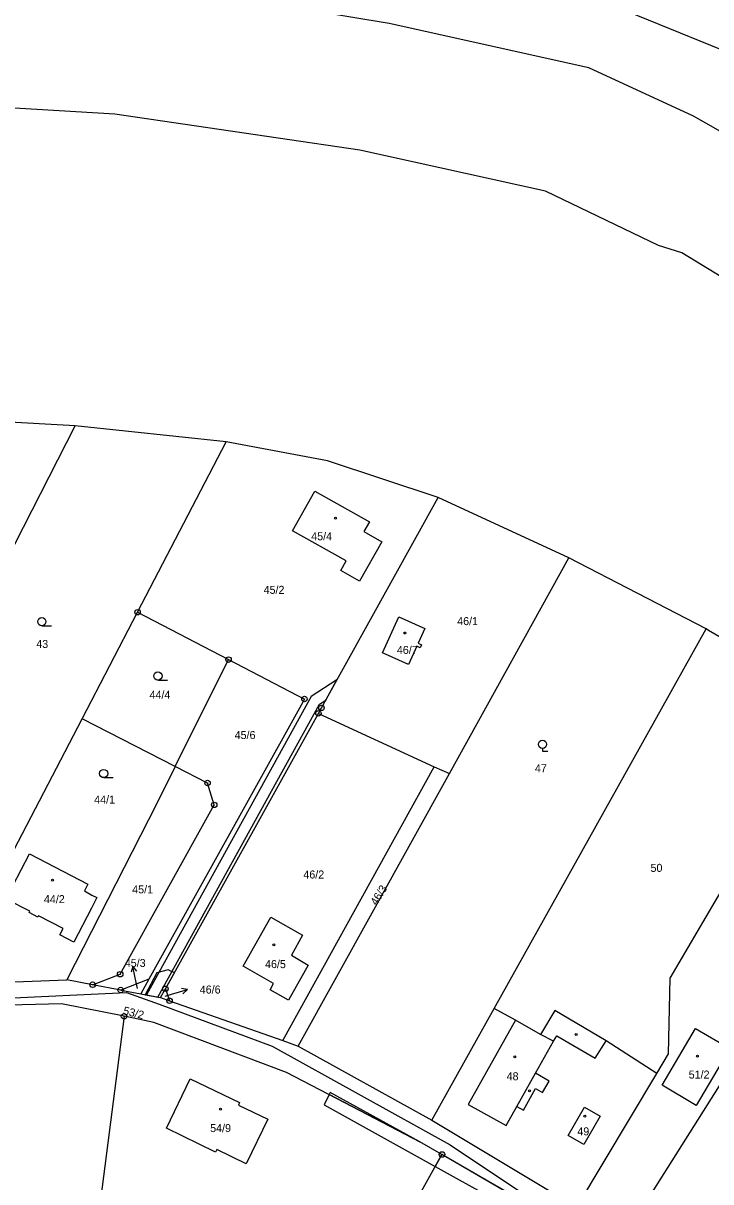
# Model space of a CAD drawing. Extents: x -587171 to -555306, y -1167727 to -1074732.
# Drawn here: x -559460.4 to -559335, y -1076430.8 to -1076219.5 of the extents above; entities that cross this region are included whole.
import ezdxf

# ---------------------------------------------------------------- set-up
doc = ezdxf.new("R2010")
doc.units = 0
for name, color, linetype in [('Hranice parcel', 7, 'Continuous'), ('Parcelní čísla', 7, 'Continuous'), ('Pop  PČ popisy', 7, 'Continuous'), ('Vnitřní kresba', 7, 'Continuous'), ('Věcná břemena k části', 7, 'Continuous'), ('Značky bodu BP', 7, 'Continuous'), ('Značky budov', 7, 'Continuous'), ('Značky kultur', 7, 'Continuous')]:
    doc.layers.add(name, color=color, linetype=linetype)

msp = doc.modelspace()

# ---------------------------------------------------------------- linework, layer by layer
at = {"layer": 'Hranice parcel'}
for p, q in [((-559450.92, -1076292.94), (-559473.66, -1076291.66)), ((-559485.29, -1076360.22), (-559450.92, -1076292.94)), ((-559423.37, -1076295.86), (-559450.92, -1076292.94)), ((-559439.53, -1076326.91), (-559423.37, -1076295.86)), ((-559360.86, -1076317.01), (-559384.7, -1076305.99)), ((-559382.67, -1076356.34), (-559360.86, -1076317.01)), ((-559335.84, -1076329.97), (-559360.86, -1076317.01)), ((-559449.65, -1076346.36), (-559439.53, -1076326.91)), ((-559439.53, -1076326.91), (-559422.93, -1076335.55)), ((-559374.52, -1076399.19), (-559335.84, -1076329.97)), ((-559432.65, -1076355.05), (-559422.93, -1076335.55)), ((-559462.83, -1076371.7), (-559449.65, -1076346.36)), ((-559432.65, -1076355.05), (-559449.65, -1076346.36)), ((-559434.45, -1076395.58), (-559406.54, -1076345.35)), ((-559406.54, -1076345.35), (-559385.42, -1076355.09)), ((-559295.54, -1076353.12), (-559351, -1076441.05)), ((-559432.65, -1076355.05), (-559436.02, -1076361.81)), ((-559426.76, -1076358.06), (-559432.65, -1076355.05)), ((-559413.05, -1076404.98), (-559385.42, -1076355.09)), ((-559385.42, -1076355.09), (-559382.67, -1076356.34)), ((-559410.23, -1076406.03), (-559382.67, -1076356.34)), ((-559436.02, -1076361.81), (-559452.4, -1076393.96)), ((-559474.85, -1076394.79), (-559452.4, -1076393.96)), ((-559447.72, -1076394.84), (-559452.4, -1076393.96)), ((-559442.6, -1076395.81), (-559447.72, -1076394.84)), ((-559437.47, -1076393.81), (-559442.6, -1076395.81)), ((-559442.6, -1076395.81), (-559438.96, -1076396.5)), ((-559437.47, -1076393.81), (-559438.96, -1076396.5)), ((-559435.34, -1076397.19), (-559434.45, -1076395.58)), ((-559434.45, -1076395.58), (-559433.69, -1076397.77)), ((-559438.96, -1076396.5), (-559435.34, -1076397.19)), ((-559435.34, -1076397.19), (-559433.69, -1076397.77)), ((-559433.69, -1076397.77), (-559413.05, -1076404.98)), ((-559385.89, -1076419.53), (-559374.52, -1076399.19)), ((-559413.05, -1076404.98), (-559410.23, -1076406.03)), ((-559410.23, -1076406.03), (-559385.89, -1076419.53)), ((-559359.39, -1076435.43), (-559344.86, -1076411.02)), ((-559385.89, -1076419.53), (-559359.39, -1076435.43)), ((-559352.65, -1076443.99), (-559384.02, -1076425.8))]:
    msp.add_line(p, q, dxfattribs=at)
for points in [[(-559593.42, -1076182.87), (-559554.97, -1076187.73), (-559493.51, -1076194.91), (-559433.37, -1076199.67), (-559391.72, -1076206.93), (-559355.84, -1076215.01), (-559333.07, -1076224.29), (-559296.15, -1076244.56), (-559247.71, -1076272.7)], [(-559240.39, -1076291.92), (-559338.12, -1076236.45), (-559357.23, -1076227.62), (-559393.62, -1076219.58), (-559434.86, -1076212.68), (-559494.41, -1076207.65), (-559564.79, -1076200.53)], [(-559252.7, -1076313.31), (-559286.15, -1076294.4), (-559340.28, -1076261.35), (-559344.5, -1076260.04), (-559365.15, -1076250.12), (-559399.01, -1076242.66), (-559443.7, -1076236.06), (-559507.72, -1076232.26), (-559566.42, -1076228.54)], [(-559384.7, -1076305.99), (-559404.88, -1076299.33), (-559423.37, -1076295.86)], [(-559401.51, -1076317.56), (-559411.27, -1076312.04), (-559407.2, -1076304.83), (-559397.26, -1076310.44), (-559398.26, -1076312.21), (-559394.97, -1076314.08), (-559399.03, -1076321.24), (-559402.48, -1076319.3), (-559401.51, -1076317.56)], [(-559406.54, -1076345.35), (-559406, -1076344.36), (-559384.7, -1076305.99)], [(-559387.98, -1076333.38), (-559388.6, -1076333.09), (-559390.13, -1076336.47), (-559394.87, -1076334.33), (-559391.86, -1076327.73), (-559387.16, -1076329.87), (-559388.36, -1076332.55), (-559387.73, -1076332.83), (-559387.98, -1076333.38)], [(-559312.85, -1076343.32), (-559335.4, -1076330.22), (-559335.84, -1076329.97)], [(-559422.93, -1076335.55), (-559409.1, -1076342.74), (-559437.47, -1076393.81)], [(-559344.86, -1076411.02), (-559342.72, -1076407.42), (-559342.37, -1076393.65), (-559312.85, -1076343.32)], [(-559447.72, -1076394.84), (-559442.7, -1076392.93), (-559425.55, -1076362.04), (-559426.76, -1076358.06)], [(-559463.52, -1076379.86), (-559463.8, -1076379.72), (-559459.23, -1076370.97), (-559448.61, -1076376.51), (-559449.22, -1076377.74), (-559447.84, -1076378.53), (-559446.95, -1076378.95), (-559447.91, -1076380.86), (-559451.16, -1076387.1), (-559453.69, -1076385.74), (-559453.11, -1076384.6), (-559457.61, -1076382.26), (-559457.73, -1076382.49), (-559459.31, -1076381.68), (-559459.2, -1076381.43), (-559463.22, -1076379.34), (-559463.52, -1076379.86)], [(-559420.28, -1076391.46), (-559415.25, -1076382.52), (-559409.44, -1076385.79), (-559411.46, -1076389.45), (-559408.41, -1076391.29), (-559412, -1076397.63), (-559415.35, -1076395.75), (-559414.72, -1076394.61), (-559420.28, -1076391.46)], [(-559529.43, -1076404.66), (-559482.86, -1076398.2), (-559441.57, -1076396.27), (-559435.57, -1076398.37), (-559414.99, -1076406.03), (-559382.52, -1076424.05), (-559352.65, -1076443.99)], [(-559441.99, -1076400.6), (-559453.4, -1076398.3), (-559474.91, -1076398.9), (-559504.91, -1076402.3), (-559529.43, -1076404.66)], [(-559344.86, -1076411.02), (-559354.09, -1076405.07), (-559363.41, -1076399.53), (-559366.07, -1076403.89), (-559370.59, -1076401.33), (-559374.52, -1076399.19)], [(-559441.99, -1076400.6), (-559446.45, -1076435.47), (-559446.5, -1076435.86)], [(-559384.02, -1076425.8), (-559388.04, -1076423.47), (-559412.35, -1076410.85), (-559436.57, -1076401.7), (-559441.99, -1076400.6)], [(-559331.54, -1076406.48), (-559337.64, -1076416.85), (-559343.84, -1076413.18), (-559337.75, -1076402.82), (-559331.54, -1076406.48)], [(-559415.77, -1076419.38), (-559419.7, -1076427.51), (-559425.07, -1076424.91), (-559425.29, -1076425.36), (-559434.28, -1076421.01), (-559429.91, -1076411.99), (-559420.92, -1076416.32), (-559421.14, -1076416.78), (-559415.77, -1076419.38)], [(-559355.14, -1076418.79), (-559358.12, -1076423.99), (-559360.98, -1076422.33), (-559358.05, -1076417.14), (-559355.14, -1076418.79)], [(-559402.27, -1076458.62), (-559385, -1076427.56), (-559384.02, -1076425.8)]]:
    msp.add_lwpolyline(points, dxfattribs=at)
at = {"layer": 'Pop  PČ popisy'}
for p, q in [((-559440.42, -1076391.49), (-559440.71, -1076392.57)), ((-559439.8, -1076394.42), (-559440.42, -1076391.49)), ((-559440.42, -1076391.49), (-559439.73, -1076392.36)), ((-559439.57, -1076395.52), (-559439.8, -1076394.42)), ((-559433.32, -1076396.55), (-559430.44, -1076395.72)), ((-559430.44, -1076395.72), (-559431.54, -1076395.52)), ((-559430.44, -1076395.72), (-559431.26, -1076396.48)), ((-559434.52, -1076396.9), (-559433.32, -1076396.55))]:
    msp.add_line(p, q, dxfattribs=at)
at = {"layer": 'Vnitřní kresba'}
for p, q in [((-559370.59, -1076401.33), (-559379.25, -1076416.66)), ((-559363.68, -1076405.15), (-559366.07, -1076403.89)), ((-559363.68, -1076405.15), (-559363.09, -1076404.16)), ((-559363.09, -1076404.16), (-559356.09, -1076408.26)), ((-559366.97, -1076410.99), (-559363.68, -1076405.15)), ((-559356.09, -1076408.26), (-559354.09, -1076405.07)), ((-559370.37, -1076417.03), (-559366.97, -1076410.99)), ((-559364.47, -1076412.41), (-559366.97, -1076410.99)), ((-559365.67, -1076414.47), (-559364.47, -1076412.41)), ((-559369.17, -1076417.71), (-559366.96, -1076413.76)), ((-559366.96, -1076413.76), (-559365.67, -1076414.47)), ((-559379.25, -1076416.66), (-559372.33, -1076420.51)), ((-559372.33, -1076420.51), (-559370.37, -1076417.03)), ((-559370.37, -1076417.03), (-559369.17, -1076417.71))]:
    msp.add_line(p, q, dxfattribs=at)
at = {"layer": 'Věcná břemena k části'}
for points in [[(-559437.93, -1076396.7), (-559435.86, -1076397.09), (-559406.36, -1076343.68), (-559405.21, -1076342.95), (-559403.17, -1076339.27), (-559407.87, -1076342.27)], [(-559438.12, -1076396.66), (-559435.34, -1076397.19), (-559434.45, -1076395.58), (-559432.82, -1076392.66), (-559433.93, -1076392.15), (-559436.04, -1076392.69)], [(-559404.39, -1076414.49), (-559404.58, -1076414.88), (-559388.04, -1076423.47)], [(-559385.24, -1076428), (-559384.02, -1076425.8), (-559388.04, -1076423.47), (-559404.58, -1076414.88), (-559405.51, -1076416.76)], [(-559353.75, -1076445.05), (-559353.12, -1076443.72), (-559367.42, -1076435.42), (-559384.02, -1076425.8), (-559385.24, -1076428), (-559374.75, -1076433.82), (-559373.73, -1076434.09)]]:
    msp.add_lwpolyline(points, close=True, dxfattribs=at)
at = {"layer": 'Značky bodu BP'}
for centre, radius in [((-559439.53, -1076326.91), 0.5), ((-559439.53, -1076326.91), 0.0303), ((-559422.93, -1076335.55), 0.5), ((-559422.93, -1076335.55), 0.0303), ((-559409.1, -1076342.74), 0.5), ((-559409.1, -1076342.74), 0.0303), ((-559406.54, -1076345.35), 0.5), ((-559406, -1076344.36), 0.5), ((-559406, -1076344.36), 0.0303), ((-559406.54, -1076345.35), 0.0303), ((-559426.76, -1076358.06), 0.5), ((-559426.76, -1076358.06), 0.0303), ((-559425.55, -1076362.04), 0.5), ((-559425.55, -1076362.04), 0.0303), ((-559442.7, -1076392.93), 0.5), ((-559442.7, -1076392.93), 0.0303), ((-559447.72, -1076394.84), 0.5), ((-559447.72, -1076394.84), 0.0303), ((-559442.6, -1076395.81), 0.5), ((-559442.6, -1076395.81), 0.0303), ((-559434.45, -1076395.58), 0.5), ((-559434.45, -1076395.58), 0.0303), ((-559433.69, -1076397.77), 0.5), ((-559433.69, -1076397.77), 0.0303), ((-559441.99, -1076400.6), 0.5), ((-559441.99, -1076400.6), 0.0303), ((-559384.02, -1076425.8), 0.5), ((-559384.02, -1076425.8), 0.0303)]:
    msp.add_circle(centre, radius, dxfattribs=at)
at = {"layer": 'Značky budov'}
for centre in [(-559403.44, -1076309.75), (-559390.76, -1076330.7), (-559455.02, -1076375.77), (-559414.66, -1076387.56), (-559359.56, -1076403.92), (-559370.75, -1076407.98), (-559337.44, -1076407.85), (-559368.03, -1076414.18), (-559424.39, -1076417.55), (-559357.97, -1076418.82)]:
    msp.add_circle(centre, 0.175, dxfattribs=at)
at = {"layer": 'Značky kultur'}
for p, q in [((-559456.99, -1076329.38), (-559455.24, -1076329.38)), ((-559435.82, -1076339.29), (-559434.07, -1076339.29)), ((-559365.68, -1076351.75), (-559365.68, -1076352.25)), ((-559365.68, -1076352.25), (-559364.68, -1076352.25)), ((-559445.7, -1076357.08), (-559443.95, -1076357.08))]:
    msp.add_line(p, q, dxfattribs=at)
for centre in [(-559456.99, -1076328.63), (-559435.82, -1076338.54), (-559365.68, -1076351), (-559445.7, -1076356.33)]:
    msp.add_circle(centre, 0.75, dxfattribs=at)

# ---------------------------------------------------------------- texts
at = {"layer": 'Parcelní čísla'}
for s, p in [('45/4', (-559407.86, -1076313.79)), ('45/2', (-559416.54, -1076323.56)), ('46/1', (-559381.24, -1076329.26)), ('43', (-559458, -1076333.43)), ('46/7', (-559392.24, -1076334.52)), ('44/4', (-559437.35, -1076342.7)), ('45/6', (-559421.82, -1076350.03)), ('47', (-559367.07, -1076356.09)), ('44/1', (-559447.44, -1076361.8)), ('46/2', (-559409.29, -1076375.47)), ('50', (-559345.98, -1076374.26)), ('45/1', (-559440.51, -1076378.18)), ('44/2', (-559456.61, -1076379.96)), ('45/3', (-559441.86, -1076391.6)), ('46/5', (-559416.28, -1076391.81)), ('46/6', (-559428.19, -1076396.45)), ('51/2', (-559339.02, -1076411.95)), ('48', (-559372.22, -1076412.26)), ('54/9', (-559426.29, -1076421.71)), ('49', (-559359.33, -1076422.31))]:
    msp.add_text(s, height=1.46, dxfattribs=at).set_placement(p)
for s, rotation, p in [('46/3', 58, (-559395.95, -1076380.49)), ('53/2', 346, (-559442.26, -1076400.21))]:
    msp.add_text(s, height=1.46, rotation=rotation, dxfattribs=at).set_placement(p)

doc.saveas('drawing.dxf')
